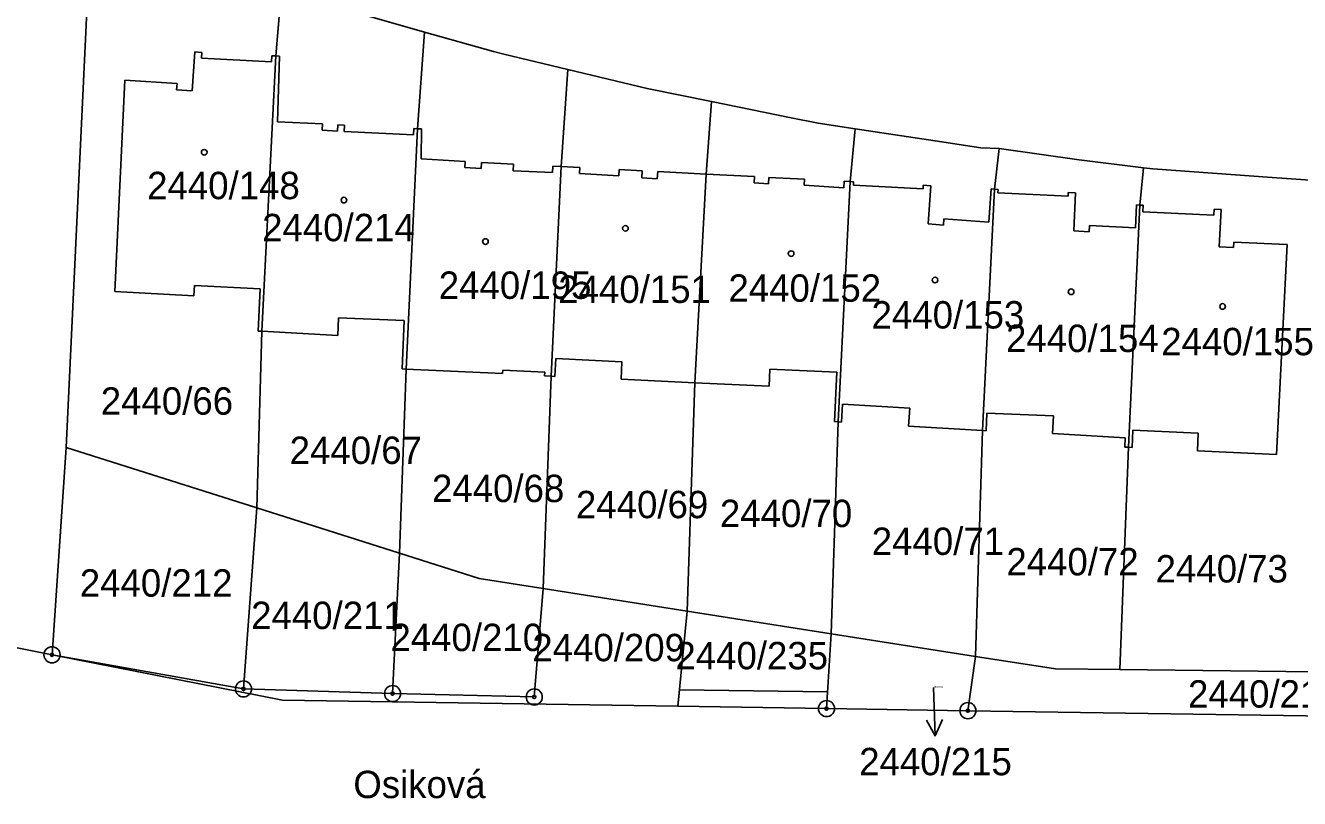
# Model space of a CAD drawing. Extents: x -755819 to -753140, y -1169796 to -1166000.
# Drawn here: x -755181.4 to -755102.2, y -1168319.1 to -1168271.1 of the extents above; entities that cross this region are included whole.
import ezdxf

# ---------------------------------------------------------------- set-up
doc = ezdxf.new("R2010")
doc.units = 0
for name, color, linetype in [('Vrstva 1', 7, 'Continuous'), ('Vrstva 15', 7, 'Continuous'), ('Vrstva 16', 7, 'Continuous'), ('Vrstva 18', 7, 'Continuous'), ('Vrstva 19', 7, 'Continuous'), ('Vrstva 24', 7, 'Continuous'), ('Vrstva 25', 7, 'Continuous'), ('Vrstva 27', 7, 'Continuous'), ('Vrstva 4', 7, 'Continuous')]:
    doc.layers.add(name, color=color, linetype=linetype)

msp = doc.modelspace()

# ---------------------------------------------------------------- linework, layer by layer
at = {"layer": 'Vrstva 1'}
for p, q in [((-755177.28, -1168264.72), (-755178.83, -1168297.33)), ((-755165.46, -1168268.88), (-755165.82, -1168273.02)), ((-755160.55, -1168270.42), (-755156.58, -1168271.54)), ((-755156.58, -1168271.54), (-755157.01, -1168277.55)), ((-755152.3, -1168272.75), (-755156.58, -1168271.54)), ((-755170.85, -1168272.78), (-755171, -1168275.19)), ((-755170.4, -1168272.81), (-755170.85, -1168272.78)), ((-755170.42, -1168273.17), (-755170.4, -1168272.81)), ((-755166.07, -1168273.39), (-755170.42, -1168273.17)), ((-755165.82, -1168273.02), (-755166.68, -1168290.12)), ((-755166.05, -1168273.01), (-755166.07, -1168273.39)), ((-755166.05, -1168273.01), (-755165.82, -1168273.02)), ((-755151.65, -1168272.91), (-755152.3, -1168272.75)), ((-755147.68, -1168273.86), (-755151.65, -1168272.91)), ((-755147.68, -1168273.86), (-755148.1, -1168279.9)), ((-755142.74, -1168275.04), (-755147.68, -1168273.86)), ((-755175.19, -1168274.53), (-755175.8, -1168287.65)), ((-755171.94, -1168274.73), (-755175.19, -1168274.53)), ((-755171.97, -1168275.13), (-755171.94, -1168274.73)), ((-755171, -1168275.19), (-755171.97, -1168275.13)), ((-755138.76, -1168275.85), (-755142.74, -1168275.04)), ((-755138.76, -1168275.85), (-755139.09, -1168280.36)), ((-755138.76, -1168275.85), (-755133.81, -1168276.86)), ((-755133.81, -1168276.86), (-755132.12, -1168277.21)), ((-755132.12, -1168277.21), (-755129.83, -1168277.55)), ((-755157.71, -1168292.47), (-755157.01, -1168277.55)), ((-755129.83, -1168277.55), (-755130.15, -1168280.83)), ((-755129.83, -1168277.55), (-755124.86, -1168278.3)), ((-755124.86, -1168278.3), (-755122.02, -1168278.73)), ((-755122.02, -1168278.73), (-755120.88, -1168278.78)), ((-755121.17, -1168281.3), (-755120.88, -1168278.78)), ((-755120.88, -1168278.78), (-755115.91, -1168279.48)), ((-755115.91, -1168279.48), (-755111.93, -1168279.97)), ((-755148.1, -1168279.9), (-755148.72, -1168292.91)), ((-755139.09, -1168280.36), (-755139.78, -1168293.32)), ((-755112.15, -1168282.29), (-755111.93, -1168279.97)), ((-755111.93, -1168279.97), (-755111.35, -1168280.04)), ((-755111.35, -1168280.04), (-755103.94, -1168280.57)), ((-755130.15, -1168280.83), (-755130.89, -1168295.75)), ((-755103.94, -1168280.57), (-755100.98, -1168280.78)), ((-755121.92, -1168296.29), (-755121.17, -1168281.3)), ((-755112.85, -1168297.32), (-755112.15, -1168282.29)), ((-755112.15, -1168282.29), (-755111.94, -1168282.3)), ((-755111.94, -1168282.3), (-755111.96, -1168282.7)), ((-755107.55, -1168282.91), (-755111.96, -1168282.7)), ((-755107.53, -1168282.54), (-755107.55, -1168282.91)), ((-755107.1, -1168282.56), (-755107.53, -1168282.54)), ((-755107.23, -1168284.88), (-755107.1, -1168282.56)), ((-755106.33, -1168284.93), (-755107.23, -1168284.88)), ((-755106.31, -1168284.58), (-755106.33, -1168284.93)), ((-755103.01, -1168284.73), (-755106.31, -1168284.58)), ((-755103.66, -1168297.77), (-755103.01, -1168284.73)), ((-755170.91, -1168287.92), (-755170.87, -1168287.27)), ((-755170.87, -1168287.27), (-755166.78, -1168287.48)), ((-755166.78, -1168287.48), (-755166.91, -1168290.11)), ((-755175.8, -1168287.65), (-755170.91, -1168287.92)), ((-755161.96, -1168290.38), (-755161.92, -1168289.28)), ((-755161.92, -1168289.28), (-755157.83, -1168289.46)), ((-755157.83, -1168289.46), (-755157.96, -1168292.46)), ((-755166.68, -1168290.12), (-755166.99, -1168301.09)), ((-755166.91, -1168290.11), (-755166.68, -1168290.12)), ((-755166.68, -1168290.12), (-755161.96, -1168290.38)), ((-755148.48, -1168292.92), (-755148.43, -1168291.81)), ((-755148.43, -1168291.81), (-755144.32, -1168292.01)), ((-755144.32, -1168292.01), (-755144.37, -1168293.1)), ((-755158.12, -1168303.91), (-755157.71, -1168292.47)), ((-755157.96, -1168292.46), (-755157.71, -1168292.47)), ((-755157.71, -1168292.47), (-755151.73, -1168292.75)), ((-755151.73, -1168292.75), (-755151.72, -1168292.54)), ((-755151.72, -1168292.54), (-755149.11, -1168292.66)), ((-755148.72, -1168292.91), (-755149.21, -1168306.1)), ((-755149.11, -1168292.66), (-755149.12, -1168292.89)), ((-755149.12, -1168292.89), (-755148.72, -1168292.91)), ((-755148.72, -1168292.91), (-755148.48, -1168292.92)), ((-755144.37, -1168293.1), (-755139.78, -1168293.32)), ((-755135.18, -1168293.54), (-755135.13, -1168292.47)), ((-755135.13, -1168292.47), (-755130.97, -1168292.66)), ((-755130.97, -1168292.66), (-755131.11, -1168295.73)), ((-755139.78, -1168293.32), (-755140.27, -1168307.5)), ((-755139.78, -1168293.32), (-755135.18, -1168293.54)), ((-755130.61, -1168294.65), (-755130.67, -1168295.76)), ((-755130.61, -1168294.65), (-755126.44, -1168294.9)), ((-755126.44, -1168294.9), (-755126.51, -1168296.01)), ((-755121.66, -1168295.2), (-755121.7, -1168296.3)), ((-755121.66, -1168295.2), (-755117.52, -1168295.38)), ((-755117.52, -1168295.38), (-755117.57, -1168296.47)), ((-755130.89, -1168295.75), (-755131.32, -1168308.9)), ((-755131.11, -1168295.73), (-755130.89, -1168295.75)), ((-755130.89, -1168295.75), (-755130.67, -1168295.76)), ((-755121.92, -1168296.29), (-755126.51, -1168296.01)), ((-755112.63, -1168297.33), (-755112.58, -1168296.26)), ((-755112.58, -1168296.26), (-755108.52, -1168296.45)), ((-755122.36, -1168310.31), (-755121.92, -1168296.29)), ((-755121.7, -1168296.3), (-755121.92, -1168296.29)), ((-755117.57, -1168296.47), (-755113.07, -1168296.74)), ((-755113.07, -1168296.74), (-755113.08, -1168297.31)), ((-755108.52, -1168296.45), (-755108.58, -1168297.54)), ((-755178.83, -1168297.33), (-755179.71, -1168310.21)), ((-755178.83, -1168297.33), (-755166.99, -1168301.09)), ((-755112.85, -1168297.32), (-755113.39, -1168311.13)), ((-755113.08, -1168297.31), (-755112.85, -1168297.32)), ((-755112.63, -1168297.33), (-755112.85, -1168297.32)), ((-755108.58, -1168297.54), (-755103.66, -1168297.77)), ((-755166.99, -1168301.09), (-755167.82, -1168312.33)), ((-755158.12, -1168303.91), (-755166.99, -1168301.09)), ((-755158.12, -1168303.91), (-755158.56, -1168312.62)), ((-755158.12, -1168303.91), (-755153.19, -1168305.48)), ((-755153.19, -1168305.48), (-755149.21, -1168306.1)), ((-755149.76, -1168312.83), (-755149.21, -1168306.1)), ((-755149.21, -1168306.1), (-755140.27, -1168307.5)), ((-755140.85, -1168313.41), (-755140.27, -1168307.5)), ((-755140.27, -1168307.5), (-755131.32, -1168308.9)), ((-755187.33, -1168308.7), (-755179.71, -1168310.21)), ((-755131.61, -1168313.55), (-755131.32, -1168308.9)), ((-755122.36, -1168310.31), (-755131.32, -1168308.9)), ((-755179.71, -1168310.21), (-755167.82, -1168312.33)), ((-755179.71, -1168310.21), (-755165.4, -1168313.03)), ((-755122.36, -1168310.31), (-755122.83, -1168313.68)), ((-755117.38, -1168311.09), (-755122.36, -1168310.31)), ((-755113.39, -1168311.13), (-755117.38, -1168311.09)), ((-755101.36, -1168311.27), (-755113.39, -1168311.13)), ((-755167.82, -1168312.33), (-755158.56, -1168312.62)), ((-755158.56, -1168312.62), (-755149.76, -1168312.83)), ((-755140.85, -1168313.41), (-755165.4, -1168313.03)), ((-755131.61, -1168313.55), (-755140.85, -1168313.41)), ((-755122.83, -1168313.68), (-755131.61, -1168313.55)), ((-755122.83, -1168313.68), (-755073.04, -1168314.44))]:
    msp.add_line(p, q, dxfattribs=at)
at = {"layer": 'Vrstva 16'}
msp.add_line((-755124.864, -1168315.248), (-755124.97, -1168312.25), dxfattribs=at)
msp.add_lwpolyline([(-755124.4, -1168314.231), (-755124.864, -1168315.248), (-755125.399, -1168314.266)], dxfattribs=at)
at = {"layer": 'Vrstva 24'}
for centre, radius in [((-755179.71, -1168310.21), 0.5), ((-755179.71, -1168310.21), 0.1), ((-755167.82, -1168312.33), 0.5), ((-755167.82, -1168312.33), 0.1), ((-755158.56, -1168312.62), 0.5), ((-755158.56, -1168312.62), 0.1), ((-755149.76, -1168312.83), 0.5), ((-755149.76, -1168312.83), 0.1), ((-755131.61, -1168313.55), 0.5), ((-755131.61, -1168313.55), 0.1), ((-755122.83, -1168313.68), 0.5), ((-755122.83, -1168313.68), 0.1)]:
    msp.add_circle(centre, radius, dxfattribs=at)
at = {"layer": 'Vrstva 25'}
for centre in [(-755170.26, -1168279.01), (-755161.58, -1168281.98), (-755144.1, -1168283.73), (-755152.79, -1168284.55), (-755133.81, -1168285.3), (-755124.87, -1168286.94), (-755116.42, -1168287.67), (-755107.01, -1168288.58)]:
    msp.add_circle(centre, 0.175, dxfattribs=at)
at = {"layer": 'Vrstva 27'}
for p, q in [((-755140.85, -1168313.41), (-755140.75, -1168312.38)), ((-755140.75, -1168312.38), (-755131.55, -1168312.51)), ((-755131.55, -1168312.51), (-755131.61, -1168313.55)), ((-755131.61, -1168313.55), (-755140.85, -1168313.41))]:
    msp.add_line(p, q, dxfattribs=at)
at = {"layer": 'Vrstva 4'}
for p, q in [((-755165.82, -1168273.02), (-755165.58, -1168273.03)), ((-755165.58, -1168273.03), (-755165.7, -1168277.12)), ((-755165.7, -1168277.12), (-755162.91, -1168277.25)), ((-755162.91, -1168277.25), (-755162.93, -1168277.64)), ((-755162.93, -1168277.64), (-755161.98, -1168277.69)), ((-755161.98, -1168277.69), (-755161.96, -1168277.3)), ((-755161.96, -1168277.3), (-755161.55, -1168277.32)), ((-755161.55, -1168277.32), (-755161.57, -1168277.72)), ((-755161.57, -1168277.72), (-755157.27, -1168277.92)), ((-755157.27, -1168277.92), (-755157.25, -1168277.54)), ((-755157.25, -1168277.54), (-755157.01, -1168277.55)), ((-755157.01, -1168277.55), (-755156.76, -1168277.56)), ((-755156.76, -1168277.56), (-755156.78, -1168279.42)), ((-755156.78, -1168279.42), (-755154.06, -1168279.59)), ((-755154.06, -1168279.59), (-755154.08, -1168279.96)), ((-755153.05, -1168280.02), (-755153.03, -1168279.64)), ((-755153.03, -1168279.64), (-755151.05, -1168279.74)), ((-755154.08, -1168279.96), (-755153.05, -1168280.02)), ((-755151.05, -1168279.74), (-755151.07, -1168280.16)), ((-755151.07, -1168280.16), (-755148.62, -1168280.27)), ((-755148.62, -1168280.27), (-755148.6, -1168279.87)), ((-755148.6, -1168279.87), (-755148.1, -1168279.9)), ((-755148.1, -1168279.9), (-755146.94, -1168279.96)), ((-755146.94, -1168279.96), (-755146.96, -1168280.33)), ((-755146.96, -1168280.33), (-755144.5, -1168280.48)), ((-755144.5, -1168280.48), (-755144.48, -1168280.08)), ((-755144.48, -1168280.08), (-755143.06, -1168280.16)), ((-755143.06, -1168280.16), (-755143.08, -1168280.59)), ((-755142.12, -1168280.65), (-755142.09, -1168280.21)), ((-755142.09, -1168280.21), (-755139.09, -1168280.36)), ((-755139.09, -1168280.36), (-755136.08, -1168280.52)), ((-755143.08, -1168280.59), (-755142.12, -1168280.65)), ((-755136.08, -1168280.52), (-755136.1, -1168280.91)), ((-755136.1, -1168280.91), (-755135.21, -1168280.96)), ((-755135.21, -1168280.96), (-755135.19, -1168280.57)), ((-755135.19, -1168280.57), (-755132.98, -1168280.68)), ((-755132.98, -1168280.68), (-755133, -1168281.05)), ((-755133, -1168281.05), (-755130.53, -1168281.21)), ((-755130.53, -1168281.21), (-755130.51, -1168280.81)), ((-755130.51, -1168280.81), (-755130.15, -1168280.83)), ((-755130.15, -1168280.83), (-755129.93, -1168280.84)), ((-755129.93, -1168280.84), (-755129.94, -1168281.06)), ((-755129.94, -1168281.06), (-755125.61, -1168281.28)), ((-755125.61, -1168281.28), (-755125.6, -1168281.06)), ((-755125.6, -1168281.06), (-755125.13, -1168281.09)), ((-755125.13, -1168281.09), (-755125.3, -1168283.46)), ((-755121.54, -1168283.34), (-755121.39, -1168281.28)), ((-755121.17, -1168281.3), (-755121.39, -1168281.28)), ((-755120.96, -1168281.31), (-755121.17, -1168281.3)), ((-755120.97, -1168281.53), (-755120.96, -1168281.31)), ((-755116.61, -1168281.74), (-755120.97, -1168281.53)), ((-755116.61, -1168281.74), (-755116.6, -1168281.51)), ((-755116.6, -1168281.51), (-755116.15, -1168281.53)), ((-755116.15, -1168281.53), (-755116.25, -1168283.89)), ((-755112.43, -1168283.7), (-755112.36, -1168282.28)), ((-755112.36, -1168282.28), (-755112.15, -1168282.29)), ((-755125.3, -1168283.46), (-755124.35, -1168283.53)), ((-755124.35, -1168283.53), (-755124.32, -1168283.14)), ((-755124.32, -1168283.14), (-755121.54, -1168283.34)), ((-755115.3, -1168283.94), (-755115.28, -1168283.56)), ((-755115.28, -1168283.56), (-755112.43, -1168283.7)), ((-755116.25, -1168283.89), (-755115.3, -1168283.94))]:
    msp.add_line(p, q, dxfattribs=at)

# ---------------------------------------------------------------- texts
at = {"layer": 'Vrstva 15'}
msp.add_text('Osiková', height=1.7, dxfattribs=at).set_placement((-755160.997, -1168319.11))
at = {"layer": 'Vrstva 16'}
msp.add_text('2440/215', height=1.7, dxfattribs=at).set_placement((-755129.582, -1168317.69))
at = {"layer": 'Vrstva 18'}
for s, height, p in [('2440/66', 1.7, (-755176.683, -1168295.3)), ('2440/67', 1.7, (-755164.952, -1168298.36)), ('2440/68', 1.7, (-755156.112, -1168300.73)), ('2440/69', 1.7, (-755147.172, -1168301.73)), ('2440/70', 1.7, (-755138.232, -1168302.28)), ('2440/71', 1.7, (-755128.802, -1168304.01)), ('2440/72', 1.7, (-755120.442, -1168305.28)), ('2440/73', 1.7, (-755111.173, -1168305.72)), ('2440/212', 1.7, (-755177.985, -1168306.6)), ('2440/211', 1.7, (-755167.343, -1168308.61)), ('2440/210', 1.7, (-755158.694, -1168309.98)), ('2440/209', 1.7, (-755149.881, -1168310.61)), ('2440/235', 1.7, (-755140.996, -1168311.11)), ('2440/216', 1.7, (-755109.16, -1168313.49)), ('2440/215', 0.1, (-755124.956, -1168312.25))]:
    msp.add_text(s, height=height, dxfattribs=at).set_placement(p)
at = {"layer": 'Vrstva 19'}
for s, p in [('2440/148', (-755173.802, -1168281.92)), ('2440/214', (-755166.66, -1168284.53)), ('2440/195', (-755155.692, -1168288.11)), ('2440/151', (-755148.27, -1168288.36)), ('2440/152', (-755137.702, -1168288.29)), ('2440/153', (-755128.812, -1168289.95)), ('2440/154', (-755120.462, -1168291.41)), ('2440/155', (-755110.822, -1168291.61))]:
    msp.add_text(s, height=1.7, dxfattribs=at).set_placement(p)

doc.saveas('drawing.dxf')
